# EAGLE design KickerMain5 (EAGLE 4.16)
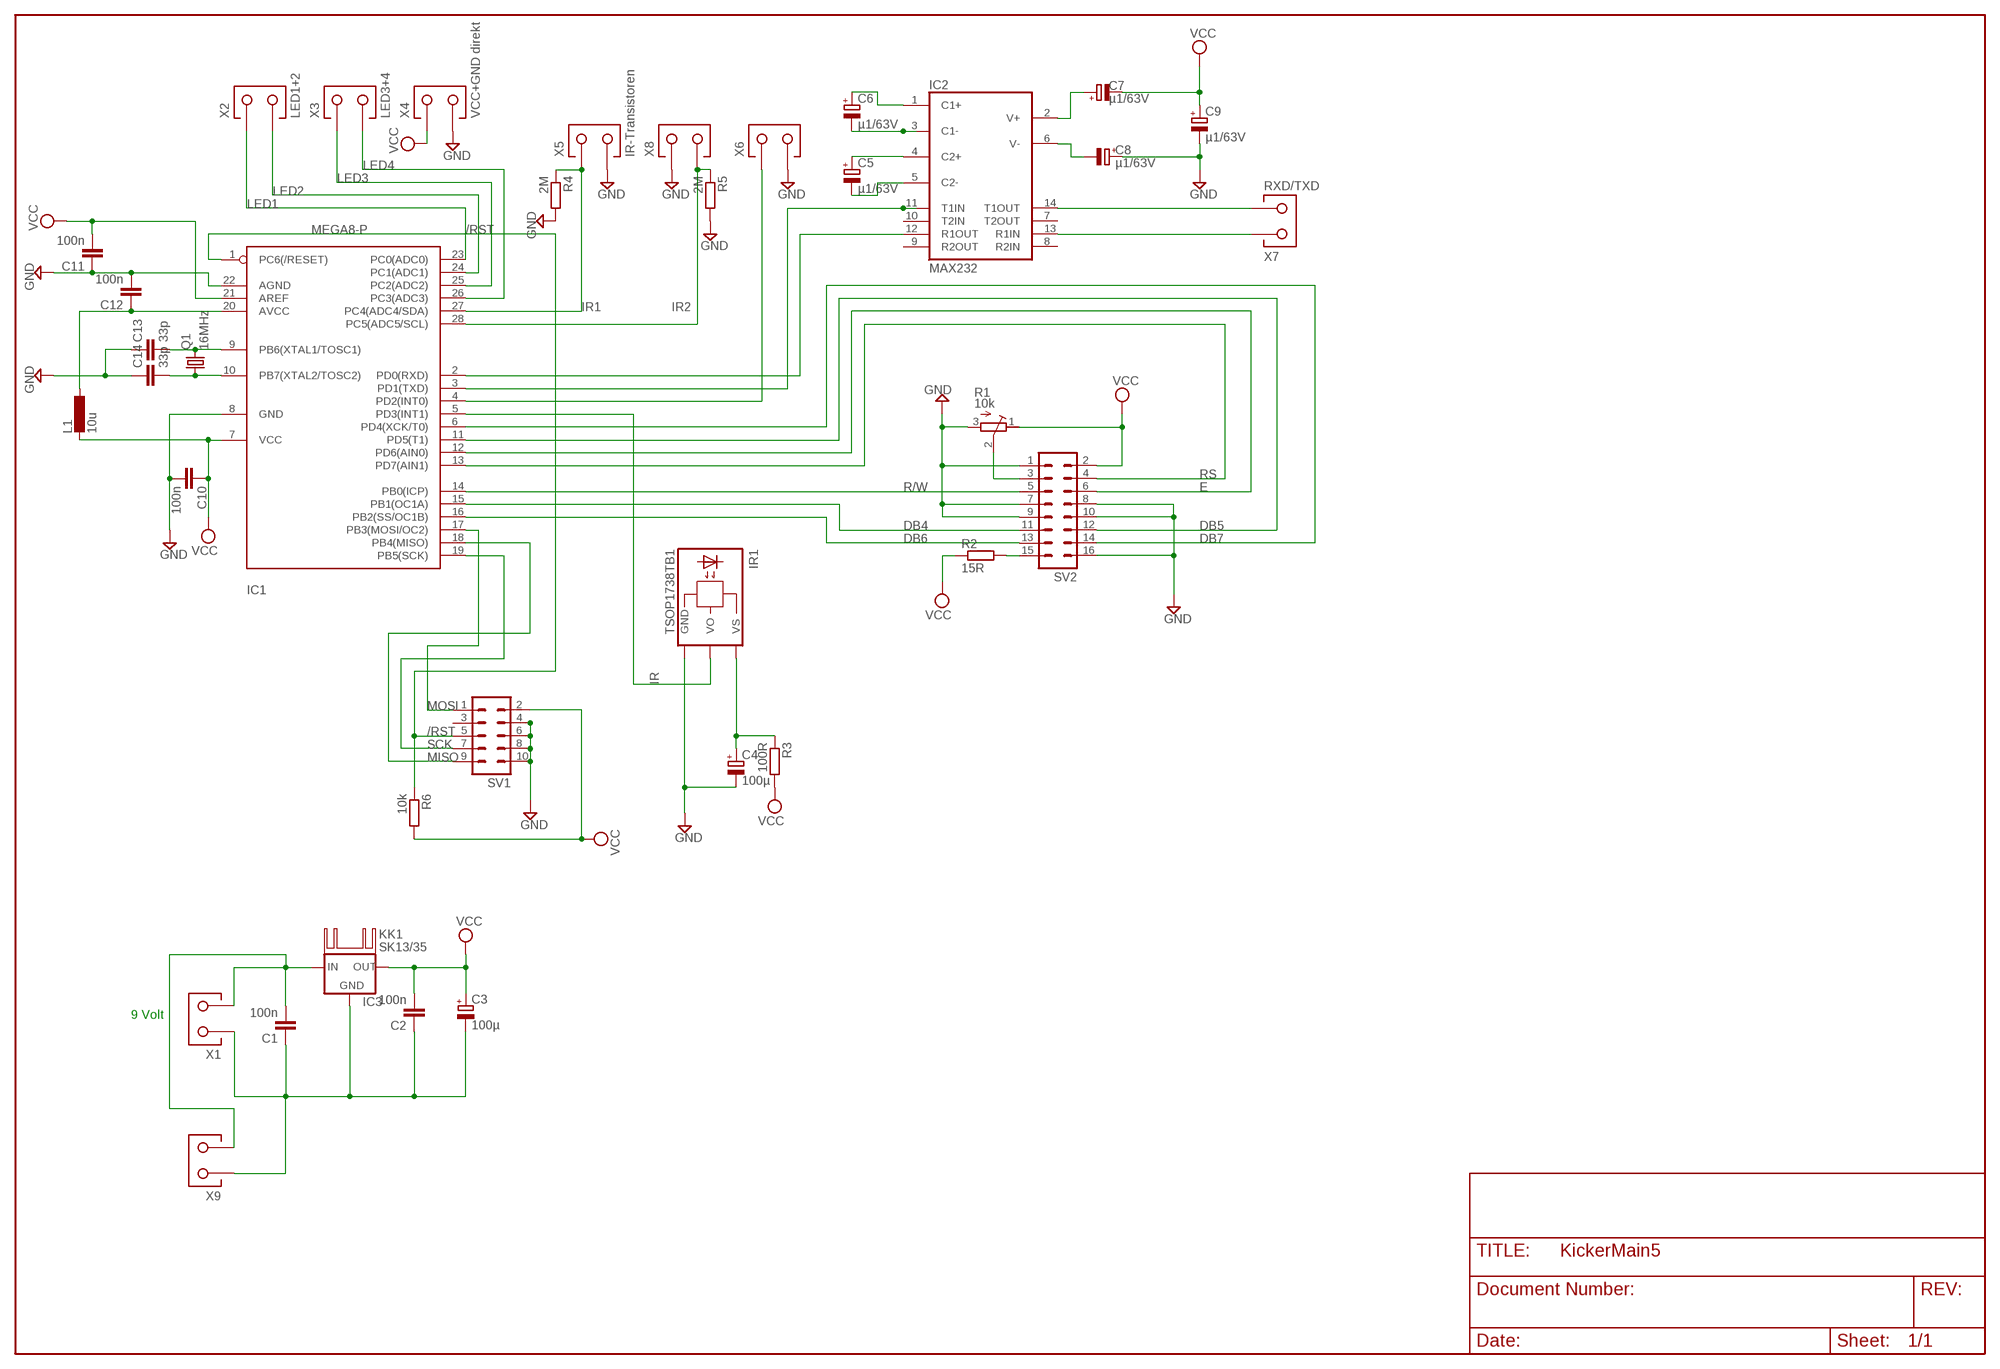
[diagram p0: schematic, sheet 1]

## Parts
C1  100n  C-EU025-025X050  [C025-025X050]
C2  100n  C-EU025-025X050  [C025-025X050]
C3  100µ  CPOL-EUE2.5-6  [E2,5-6]
C4  100µ  CPOL-EUE2.5-6  [E2,5-6]
C5  µ1/63V  C-POLE2,5-4  [E040/025]
C6  µ1/63V  C-POLE2,5-4  [E040/025]
C7  µ1/63V  C-POLE2,5-4  [E040/025]
C8  µ1/63V  C-POLE2,5-4  [E040/025]
C9  µ1/63V  C-POLE2,5-4  [E040/025]
C10  100n  C-EU025-025X050  [C025-025X050]
C11  100n  C-EU025-025X050  [C025-025X050]
C12  100n  C-EU025-025X050  [C025-025X050]
C13  33p  C-EUC1206K  [C1206K]
C14  33p  C-EUC1206K  [C1206K]
IC1  MEGA8-P  [DIL28-3]
IC2  MAX232  [DIL16]
IC3  78XXL  [78XXL]
IR1  TSOP1738TB1  [TSOP17_TB1]
KK1  SK13/35  [SK13/35]
L1  10u  L-EU0207/12  [0207/12]
Q1  16MHz  CRYTALHC49U-V  [HC49U-V]
R1  10k  R-TRIMMT93YB  [RTRIMT93YB]
R2  15R  R-EU_0207/10  [0207/10]
R3  100R  R-EU_0207/10  [0207/10]
R4  2M  R-EU_0207/10  [0207/10]
R5  2M  R-EU_0207/10  [0207/10]
R6  10k  R-EU_0207/10  [0207/10]
SV1  ML10  [ML10]
SV2  ML16  [ML16]
X1  AKL-2_3,5  [AKL-2_3,5]
X2  LED1+2  AKL-2_3,5  [AKL-2_3,5]
X3  LED3+4  AKL-2_3,5  [AKL-2_3,5]
X4  VCC+GND direkt  AKL-2_3,5  [AKL-2_3,5]
X5  IR-Transistoren  AKL-2_3,5  [AKL-2_3,5]
X6  AKL-2_3,5  [AKL-2_3,5]
X7  RXD/TXD  AKL-2_3,5  [AKL-2_3,5]
X8  AKL-2_3,5  [AKL-2_3,5]
X9  AKL-2_3,5  [AKL-2_3,5]

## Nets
+9V: C1.2 IC3.IN X1.P$2 X9.P$2
/RST: IC1.1(PC6(/RESET)) R6.1 SV1.5
AVCC: C12.1 IC1.20(AVCC) L1.1
DB4: IC1.15(PB1(OC1A)) SV2.11
DB5: IC1.11(PD5(T1)) SV2.12
DB6: IC1.16(PB2(SS/OC1B)) SV2.13
DB7: IC1.6(PD4(XCK/T0)) SV2.14
E: IC1.12(PD6(AIN0)) SV2.6
GND: C1.1 C2.1 C3.- C4.- C8.P$1(+) C9.P$2(-) C10.2 C11.1 C12.2 C13.1 C14.1 IC1.8(GND) IC1.22(AGND) IC3.GND IR1.GND R1.3(E) R4.2 R5.2 SV1.4 SV1.6 SV1.8 SV1.10 SV2.1 SV2.7 SV2.8 SV2.9 SV2.10 SV2.16 X1.P$1 X4.P$2 X5.P$2 X6.P$2 X8.P$1 X9.P$1
IO: IC1.4(PD2(INT0)) X6.P$1
IR: IC1.5(PD3(INT1)) IR1.VO
IR1: IC1.27(PC4(ADC4/SDA)) R4.1 X5.P$1
IR2: IC1.28(PC5(ADC5/SCL)) R5.1 X8.P$2
LED1: IC1.23(PC0(ADC0)) X2.P$1
LED2: IC1.24(PC1(ADC1)) X2.P$2
LED3: IC1.25(PC2(ADC2)) X3.P$1
LED4: IC1.26(PC3(ADC3)) X3.P$2
MISO: IC1.18(PB4(MISO)) SV1.9
MOSI: IC1.17(PB3(MOSI/OC2)) SV1.1
N$1: IC2.13(R1IN) X7.P$1
N$2: R2.2 SV2.15
N$4: R1.2(S) SV2.3
N$6: C6.P$2(-) IC2.3(C1-)
N$7: C6.P$1(+) IC2.1(C1+)
N$8: C5.P$1(+) IC2.4(C2+)
N$9: C5.P$2(-) IC2.5(C2-)
N$10: C7.P$1(+) IC2.2(V+)
N$11: C8.P$2(-) IC2.6(V-)
N$14: IC1.2(PD0(RXD)) IC2.12(R1OUT)
N$18: C4.+ IR1.VS R3.1
N$24: IC1.3(PD1(TXD)) IC2.11(T1IN)
PCP2: IC2.14(T1OUT) X7.P$2
R/W: IC1.14(PB0(ICP)) SV2.5
RS: IC1.13(PD7(AIN1)) SV2.4
SCK: IC1.19(PB5(SCK)) SV1.7
VCC: C2.2 C3.+ C7.P$2(-) C9.P$1(+) C10.1 C11.2 IC1.7(VCC) IC1.21(AREF) IC3.OUT L1.2 R1.1(A) R2.1 R3.2 R6.2 SV1.2 SV2.2 X4.P$1
XTAL1: C13.2 IC1.9(PB6(XTAL1/TOSC1)) Q1.2
XTAL2: C14.2 IC1.10(PB7(XTAL2/TOSC2)) Q1.1
Unconnected: IC2.7(T2OUT) IC2.8(R2IN) IC2.9(R2OUT) IC2.10(T2IN) SV1.3

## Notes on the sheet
- 9 Volt

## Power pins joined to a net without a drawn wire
GND: IC2.15(GND)
VCC: IC2.16(VCC)

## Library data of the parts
C1 C2 C10-C14 = rcl:C-EU: CAPACITOR, European symbol
C3 C4 = rcl:CPOL-EU: POLARIZED CAPACITOR, European symbol
C5-C9 = EWM-rcl:C-POL: Elko
IC1 = atmel:MEGA8-P: MICROCONTROLLER 8 Kbytes FLASH 1 kbytes SRAM 512 bytes EEPROM USART 4-channel 10 bit ADC 2-channel 8 bit ADC Source: avr.lbr
IC2 = maxim:MAX232: RS232 TRANSEIVER
IC3 = v-reg:78XXL: VOLTAGE REGULATOR
IR1 = telefunken:TSOP17*TB1: TSOP17..TB1 IR Receiver Modules for Remote Control Systems Source: http://www.vishay.com/docs/82042/82042.pdf
KK1 = heatsink:SK13/35: HEATSINK
L1 = rcl:L-EU: INDUCTOR, European symbol
Q1 = crystal:CRYTAL: CRYSTAL
R1 = rcl:R-TRIMM: Trimm resistor
R2-R6 = rcl:R-EU_: RESISTOR, European symbol
SV1 = con-harting-ml:ML10: HARTING
SV2 = con-harting-ml:ML16: HARTING
X1-X9 = 0mylib:AKL-2_3,5

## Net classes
0 default: width 0.356 mm, drill 0.254 mm, clearance 0.61 mm
1 GND: width 0.991 mm, drill 0.254 mm, clearance 0.61 mm
2 VCC: width 0.356 mm, drill 0.254 mm, clearance 0.61 mm
3 breit2: width 2.032 mm, drill 0.483 mm, clearance 0.61 mm
4 breit3: width 2.54 mm, drill 0.61 mm, clearance 0.61 mm

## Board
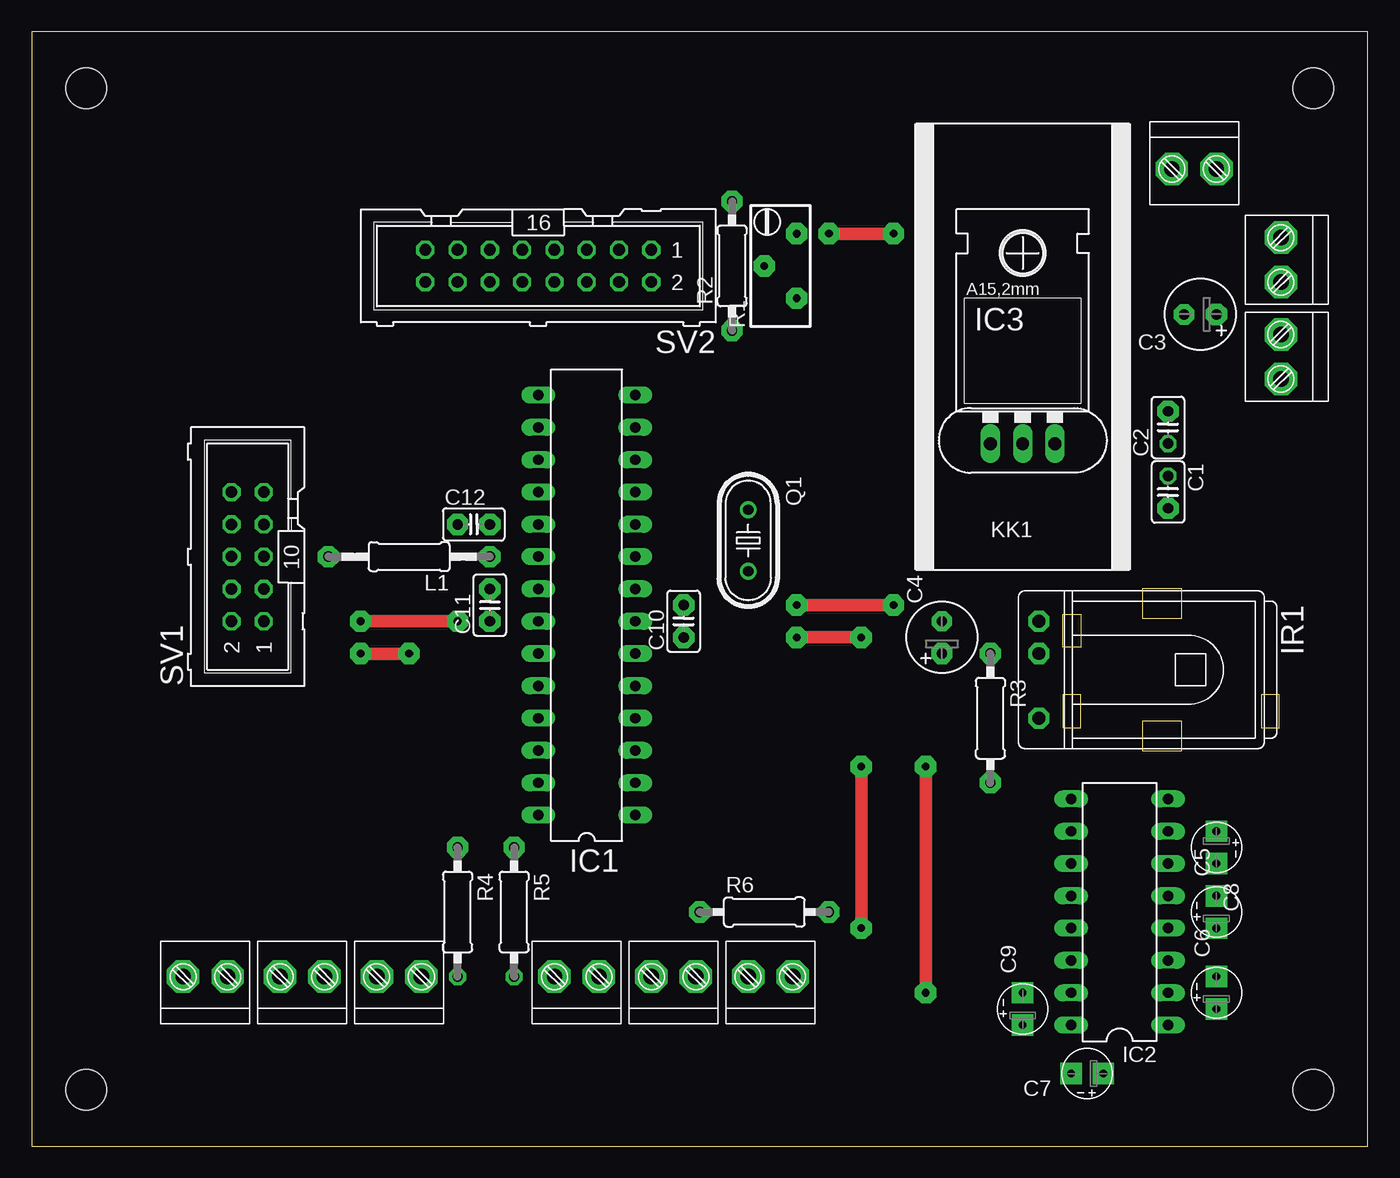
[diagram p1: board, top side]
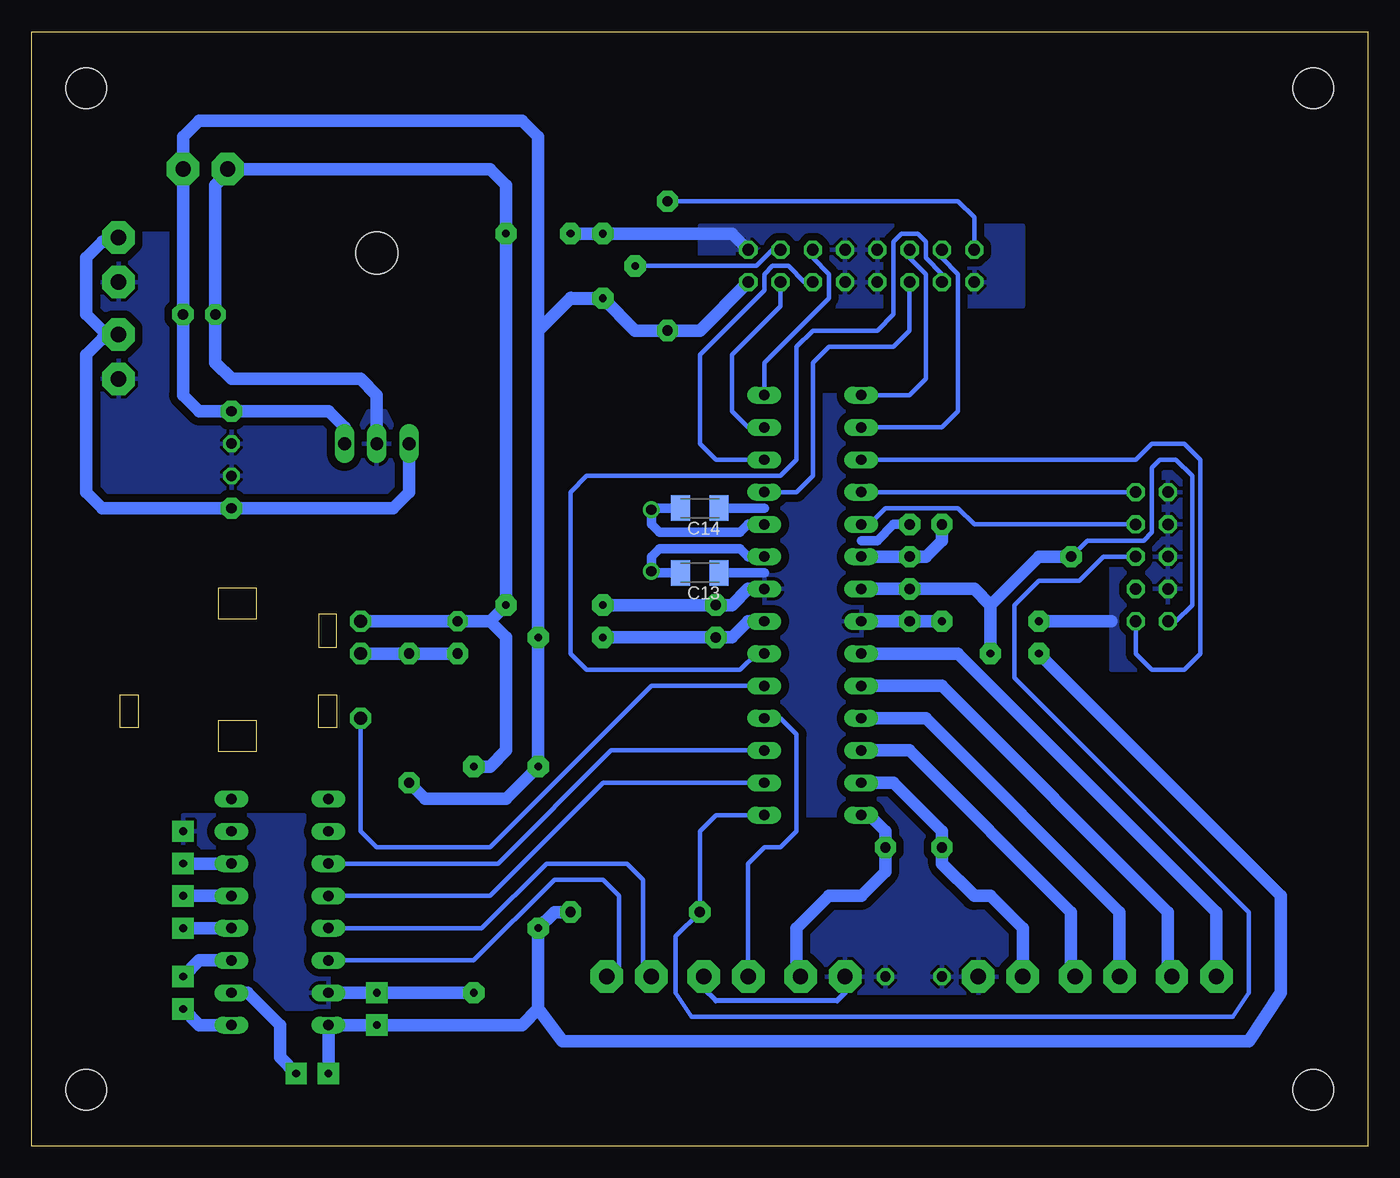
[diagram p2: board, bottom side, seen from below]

Size 105.08 x 87.62 mm. Coordinates in mm from the lower left corner, seen from the top.
Outline: 0,0 105.08,0 105.08,87.62 0,87.62 0,0
Copper layers (1*16): Top 0.035mm / dielectric 1.5mm / Bottom 0.035mm
Design rules "default": minimum track width 10mil, minimum drill 24mil, track to track 8mil, track to pad 8mil, pad to pad 8mil, via to via 8mil, smd to smd 8mil, copper to edge 40mil, drill to drill 8mil, minimum pad ring 10mil, minimum via ring 8mil, stop-mask expansion 4mil, vias tented up to drill 0mil, thermal gap 10mil
Holes 3.2 mm at 4.28,83.18 4.28,4.44 100.8,83.18 100.8,4.44

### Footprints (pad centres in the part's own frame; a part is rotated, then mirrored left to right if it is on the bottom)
C025-025X050 = drill 0.813 octagon: 1 -1.27,0; 2 1.27,0
E2,5-6 = drill 0.813 pad 1.6 round: + -1.27,0 | drill 0.813 pad 1.6 octagon: - 1.27,0
E040/025 = drill 0.61 pad 1.676 square: P$1 -1.27,0; P$2 1.27,0
C1206K = smd 1.5 x 2: 1 -1.5,0; 2 1.5,0
DIL28-3 = drill 0.813 long: 1 -16.51,-3.81; 2 -13.97,-3.81; 3 -11.43,-3.81; 4 -8.89,-3.81; 5 -6.35,-3.81; 6 -3.81,-3.81; 7 -1.27,-3.81; 8 1.27,-3.81; 9 3.81,-3.81; 10 6.35,-3.81; 11 8.89,-3.81; 12 11.43,-3.81; 13 13.97,-3.81; 14 16.51,-3.81; 15 16.51,3.81; 16 13.97,3.81; 17 11.43,3.81; 18 8.89,3.81; 19 6.35,3.81; 20 3.81,3.81; 21 1.27,3.81; 22 -1.27,3.81; 23 -3.81,3.81; 24 -6.35,3.81; 25 -8.89,3.81; 26 -11.43,3.81; 27 -13.97,3.81; 28 -16.51,3.81
DIL16 = drill 0.813 long: 1 -8.89,-3.81; 2 -6.35,-3.81; 3 -3.81,-3.81; 4 -1.27,-3.81; 5 1.27,-3.81; 6 3.81,-3.81; 7 6.35,-3.81; 8 8.89,-3.81; 9 8.89,3.81; 10 6.35,3.81; 11 3.81,3.81; 12 1.27,3.81; 13 -1.27,3.81; 14 -3.81,3.81; 15 -6.35,3.81; 16 -8.89,3.81
78XXL = drill 1.016 long: GND 0,-3.81; IN -2.54,-3.81; OUT 2.54,-3.81 | hole 3.302: 0,11.176
TSOP17_TB1 = drill 1 pad 1.676 round: GND 0,-3.81; VO 0,3.81; VS 0,-1.27
0207/12 = drill 0.813 octagon: 1 -6.35,0; 2 6.35,0
HC49U-V = drill 0.813 round: 1 -2.413,0; 2 2.413,0
RTRIMT93YB = drill 0.61 round: 1 1.27,-2.54; 2 -1.27,0; 3 1.27,2.54
0207/10 = drill 0.813 octagon: 1 -5.08,0; 2 5.08,0
ML10 = drill 0.914 octagon: 1 -5.08,-1.27; 2 -5.08,1.27; 3 -2.54,-1.27; 4 -2.54,1.27; 5 0,-1.27; 6 0,1.27; 7 2.54,-1.27; 8 2.54,1.27; 9 5.08,-1.27; 10 5.08,1.27
ML16 = drill 0.914 octagon: 1 -8.89,-1.27; 2 -8.89,1.27; 3 -6.35,-1.27; 4 -6.35,1.27; 5 -3.81,-1.27; 6 -3.81,1.27; 7 -1.27,-1.27; 8 -1.27,1.27; 9 1.27,-1.27; 10 1.27,1.27; 11 3.81,-1.27; 12 3.81,1.27; 13 6.35,-1.27; 14 6.35,1.27; 15 8.89,-1.27; 16 8.89,1.27
AKL-2_3,5 = drill 1.2 pad 2.54 octagon: P$1 0,0; P$2 3.5,0

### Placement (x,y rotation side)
C1  89.37,51.43 270 top
C2  89.37,56.51 90 top
C3  91.91,65.4 180 top
C4  71.59,40 90 top
C5  93.18,18.41 90 top
C6  93.18,12.06 90 top
C7  83.02,5.71 180 top
C8  93.18,23.49 270 top
C9  77.94,10.79 90 top
C10  51.27,41.27 90 top
C11  36.03,42.54 90 top
C12  34.76,48.89 0 top
C13  52.54,45.08 180 bottom
C14  52.54,50.16 180 bottom
IC1  43.65,42.54 90 top
IC2  85.56,18.41 90 top
IC3  77.94,59.05 0 top
IR1  79.21,37.46 180 top
KK1  77.94,59.05 270 top
L1  29.68,46.35 180 top
Q1  56.35,47.62 270 top
R1  58.89,69.21 0 top
R2  55.08,69.21 90 top
R3  75.4,33.65 270 top
R4  33.49,18.41 270 top
R5  37.94,18.41 270 top
R6  57.62,18.41 0 top
SV1  16.98,46.35 90 top
SV2  39.84,69.21 180 top
X1  98.26,60.32 90 top
X2  11.9,13.33 0 top
X3  19.52,13.33 0 top
X4  93.18,76.83 180 top
X5  27.14,13.33 0 top
X6  48.73,13.33 0 top
X7  56.35,13.33 0 top
X8  41.11,13.33 0 top
X9  98.26,67.94 90 top

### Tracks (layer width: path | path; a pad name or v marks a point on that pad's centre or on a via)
+9V  (via drill 0.6 pad 1.68)
  Bottom 0.991: X9.P$2 98.26,71.11 99.53,71.11 100.8,69.84 100.8,65.4 99.22,63.82 X1.P$2 98.26,63.49 99.53,63.49 100.8,62.22 100.8,51.43 99.53,50.16 C1.2 76.67,50.16 75.4,51.43 IC3.IN
  other vias: 89.37,50.16
/RST  (via drill 0.6 pad 1.68)
  Bottom 0.356: IC1.1 51.27,26.03 52.54,24.76 R6.1 54.45,16.5 54.45,12.06 53.18,10.16 10.63,10.16 9.36,12.06 9.36,18.41 27.78,36.82 27.78,42.54 25.87,44.45 22.7,44.45 20.79,46.35 SV1.5
  other vias: 52.54,18.41
AVCC
  Bottom 0.991: C12.1 33.49,47.62 34.76,46.35 L1.1 IC1.20
DB4
  Bottom 0.356: SV2.11 36.03,69.84 34.76,68.58 34.76,60.32 36.03,59.05 IC1.15
DB5
  Bottom 0.356: IC1.11 44.92,51.43 43.65,52.7 43.65,61.59 42.38,62.86 37.3,62.86 36.03,64.13 SV2.12
DB6
  Bottom 0.356: SV2.13 33.49,69.84 32.22,68.58 32.22,57.78 33.49,56.51 IC1.16
DB7
  Bottom 0.356: IC1.6 48.09,38.73 49.37,37.46 61.43,37.46 62.7,38.73 62.7,51.43 61.43,52.7 46.19,52.7 44.92,53.97 44.92,62.86 43.65,64.13 38.57,64.13 37.3,65.4 37.3,71.11 36.66,71.75 35.39,71.75 34.76,71.11 34.76,69.84 33.49,68.58 SV2.14
E
  Bottom 0.356: IC1.12 51.27,53.97 52.54,55.24 52.54,62.22 47.46,67.31 47.46,68.58 46.83,69.21 45.55,69.21 44.29,67.94 SV2.6
GND  (via drill 0.6 pad 1.68)
  Top 0.991: v70.32,12.06 v70.32,29.84 | v67.78,71.75 v62.7,71.75 | v25.87,41.27 v33.49,41.27 | v67.78,42.54 v60.16,42.54
  Bottom 0.406: X6.P$2 52.23,12.39 51.27,11.43 41.75,11.43 41.11,12.06 X8.P$1
  Bottom 0.762: 47.46,50.16 C14.1 | 47.46,45.08 C13.1 | C12.2 37.3,48.89 38.57,47.62 39.84,47.62
  Bottom 0.991: IC1.8 48.73,43.81 50,42.54 C10.2 v60.16,42.54 | SV2.1 50,71.75 R1.3 v62.7,71.75 | IC2.15 C9.P$2 v70.32,12.06 | IR1.GND C4.- 69.05,41.27 | 69.05,41.27 67.78,40 67.78,31.11 69.05,29.84 v70.32,29.84 | IC3.GND 77.94,59.05 79.21,60.32 89.37,60.32 90.64,61.59 C3.- 90.64,75.56 89.37,76.83 | 89.37,76.83 X4.P$2 | 89.37,76.83 69.05,76.83 67.78,75.56 v67.78,71.75 v67.78,42.54 69.05,41.27 | v33.49,41.27 C11.1 IC1.22 | 20.16,41.27 v25.87,41.27
  pour Bottom (isolate 0.406): 83.66,26.03 83.66,14.6 81.75,14.6 81.75,10.79 87.47,10.79 87.47,22.22 89.37,22.22 89.37,23.49 93.81,23.49 93.81,25.39 93.18,26.03
  pour Bottom: 39.84,59.05 39.84,26.03 47.46,26.03 47.46,59.05
  pour Bottom: 27.14,72.38 27.14,66.03 52.54,66.03 52.54,72.38
  pour Bottom (isolate 0.406): 93.18,71.75 98.26,71.75 99.53,71.11 99.53,50.16 76.67,50.16 75.4,51.43 75.4,55.24 76.67,56.51 77.31,57.78 78.58,57.78 79.21,56.51 80.48,56.51 81.75,57.78 91.28,57.78 93.18,59.68
  pour Bottom: 13.8,55.24 13.8,37.46 20.16,37.46 20.16,55.24
  pour Bottom: 27.14,12.06 27.14,17.14 29.68,19.68 30.95,19.68 33.49,22.22 33.49,24.76 37.3,28.57 42.38,28.57 42.38,26.03 39.2,26.03 37.94,24.76 37.94,21.59 39.84,19.68 42.38,19.68 44.92,17.14 44.92,12.06
IO
  Bottom 0.356: IC1.4 46.19,33.65 44.92,32.38 44.92,24.76 46.19,23.49 47.46,23.49 48.73,22.22 X6.P$1
IR
  Bottom 0.356: IC1.5 56.35,36.19 69.05,23.49 77.94,23.49 79.21,24.76 IR1.VO
IR1
  Bottom 0.991: X5.P$1 27.14,17.14 29.68,19.68 30.95,19.68 33.49,22.22 R4.1 33.49,24.76 37.3,28.57 IC1.27
IR2
  Bottom 0.356: X8.P$2 44.92,13.33
  Bottom 0.991: 44.92,13.33 44.92,17.14 42.38,19.68 39.84,19.68 37.94,21.59 R5.1 37.94,24.76 39.2,26.03 IC1.28
LED1
  Bottom 0.991: IC1.23 32.22,38.73 11.9,18.41 X2.P$1
LED2
  Bottom 0.356: X2.P$2 15.71,13.33
  Bottom 0.991: IC1.24 33.49,36.19 15.71,18.41 15.71,13.33
LED3
  Bottom 0.991: IC1.25 34.76,33.65 19.52,18.41 X3.P$1
LED4
  Bottom 0.356: X3.P$2 23.33,13.33
  Bottom 0.991: IC1.26 36.03,31.11 23.33,18.41 23.33,13.33
MISO
  Bottom 0.356: SV1.9 IC1.18
MOSI
  Bottom 0.356: SV1.1 18.25,38.73 16.98,37.46 14.44,37.46 13.17,38.73 13.17,53.97 14.44,55.24 16.98,55.24 18.25,53.97 IC1.17
N$1
  Bottom 0.356: IC2.13 69.69,17.14 64.61,22.22 58.26,22.22 56.98,20.95 56.98,13.96 X7.P$1
N$2
  Bottom 0.356: R2.2 32.22,74.29 30.95,73.02 SV2.15
N$3  (via drill 0.6 pad 1.68)
  other vias: 60.16,66.67
N$4
  Bottom 0.356: R1.2 48.09,69.21 46.83,70.48 SV2.3
N$5  (via drill 0.6 pad 1.68)
  other vias: 57.62,69.21
N$6
  Bottom 0.991: IC2.3 91.91,14.6 C6.P$2
N$7
  Bottom 0.991: IC2.1 91.91,9.52 C6.P$1
N$8
  Bottom 0.991: IC2.4 C5.P$1
N$9
  Bottom 0.991: IC2.5 C5.P$2
N$10
  Bottom 0.991: IC2.2 88.1,12.06 85.56,9.52 85.56,6.98 C7.P$1
N$11
  Bottom 0.991: IC2.6 C8.P$2
N$12  (via drill 0.6 pad 1.68)
  other vias: 60.16,71.75
N$13  (via drill 0.6 pad 1.68)
  other vias: 36.03,43.81
N$14
  Bottom 0.356: IC1.2 60.16,28.57 69.05,19.68 IC2.12
N$15  (via drill 0.6 pad 1.68)
  other vias: 55.08,64.13
N$16  (via drill 0.6 pad 1.68)
  other vias: 55.08,74.29
N$17  (via drill 0.6 pad 1.68)
  other vias: 33.49,23.49
N$18
  Bottom 0.991: C4.+ R3.1 IR1.VS
N$19  (via drill 0.6 pad 1.68)
  other vias: 37.94,23.49
N$20  (via drill 0.6 pad 1.68)
  other vias: 71.59,38.73
N$21  (via drill 0.6 pad 1.68)
  other vias: 36.03,46.35
N$22  (via drill 0.6 pad 1.68)
  other vias: 75.4,28.57
N$23  (via drill 0.6 pad 1.68)
  other vias: 75.4,38.73
N$24
  Bottom 0.356: IC1.3 59.52,31.11 68.42,22.22 IC2.11
N$25  (via drill 0.6 pad 1.68)
  other vias: 79.21,33.65
N$26  (via drill 0.6 pad 1.68)
  other vias: 62.7,18.41
N$28  (via drill 0.6 pad 1.68)
  other vias: 79.21,38.73
N$29  (via drill 0.6 pad 1.68)
  other vias: 79.21,41.27
N$30  (via drill 0.6 pad 1.68)
  other vias: 33.49,48.89
N$31  (via drill 0.6 pad 1.68)
  other vias: 36.03,48.89
N$32  (via drill 0.6 pad 1.68)
  other vias: 36.03,41.27
N$33  (via drill 0.6 pad 1.68)
  other vias: 51.27,42.54
N$34  (via drill 0.6 pad 1.68)
  other vias: 51.27,40
PCP2
  Bottom 0.356: IC2.14 70.32,14.6 63.97,20.95 60.16,20.95 58.89,19.68 58.89,13.96 59.52,13.33 X7.P$2
R/W
  Bottom 0.356: SV2.5 43.65,69.84 42.38,68.58 42.38,66.67 47.46,61.59 IC1.14
RS
  Bottom 0.356: SV2.4 46.19,66.03 50,62.22 50,57.78 48.73,56.51 IC1.13
SCK
  Bottom 0.356: SV1.7 30.95,48.89 32.22,50.16 37.94,50.16 39.2,48.89 IC1.19
VCC  (via drill 0.6 pad 1.68)
  Top 0.991: v65.24,17.14 v65.24,29.84 | v65.24,40 v60.16,40 | v25.87,38.73 v29.68,38.73
  Bottom 0.356: L1.2 22.06,47.62 17.62,47.62 16.98,48.25 16.98,53.34 16.34,53.97 15.07,53.97 13.8,52.7 13.8,42.54 15.07,41.27 SV1.2
  Bottom 0.991: IC1.7 48.73,41.27 50,40 C10.1 v60.16,40 | R1.1 57.62,64.13 52.54,64.13 | C7.P$2 IC2.16 C9.P$1 66.51,9.52 65.24,10.79 | 29.68,42.54 25.87,46.35 L1.2 | IC1.21 C11.2 30.95,43.81 29.68,42.54 | R6.2 63.97,18.41 v65.24,17.14 65.24,10.79 | v65.24,29.84 v65.24,40 | 52.54,64.13 R2.1 | 52.54,64.13 SV2.2 | IC3.OUT 80.48,56.51 81.75,57.78 C2.2 91.91,57.78 93.18,59.05 C3.+ X4.P$1 93.18,79.37 91.91,80.64 66.51,80.64 65.24,79.37 65.24,64.13 v65.24,40 | v65.24,29.84 v65.24,40 | v65.24,29.84 67.78,27.3 74.13,27.3 R3.2 | v25.87,38.73 6.82,19.68 6.82,12.06 9.36,8.25 63.34,8.25 65.24,10.79 | v29.68,38.73 29.68,42.54
  Bottom 1.016: R1.1 62.7,66.67 65.24,64.13
  other vias: 23.33,46.35 89.37,57.78 93.18,65.4
XTAL1
  Bottom 0.762: IC1.9 48.73,46.35 49.37,46.98 55.72,46.98 56.35,46.35 Q1.2 | 56.35,45.08 C13.2
  Bottom 0.991: Q1.2 56.35,45.08 | C13.2 54.45,45.08
XTAL2
  Bottom 0.762: Q1.1 56.35,48.89 55.72,48.25 49.37,48.25 48.73,48.89 IC1.10 | 56.35,50.16 C14.2
  Bottom 0.991: Q1.1 56.35,50.16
